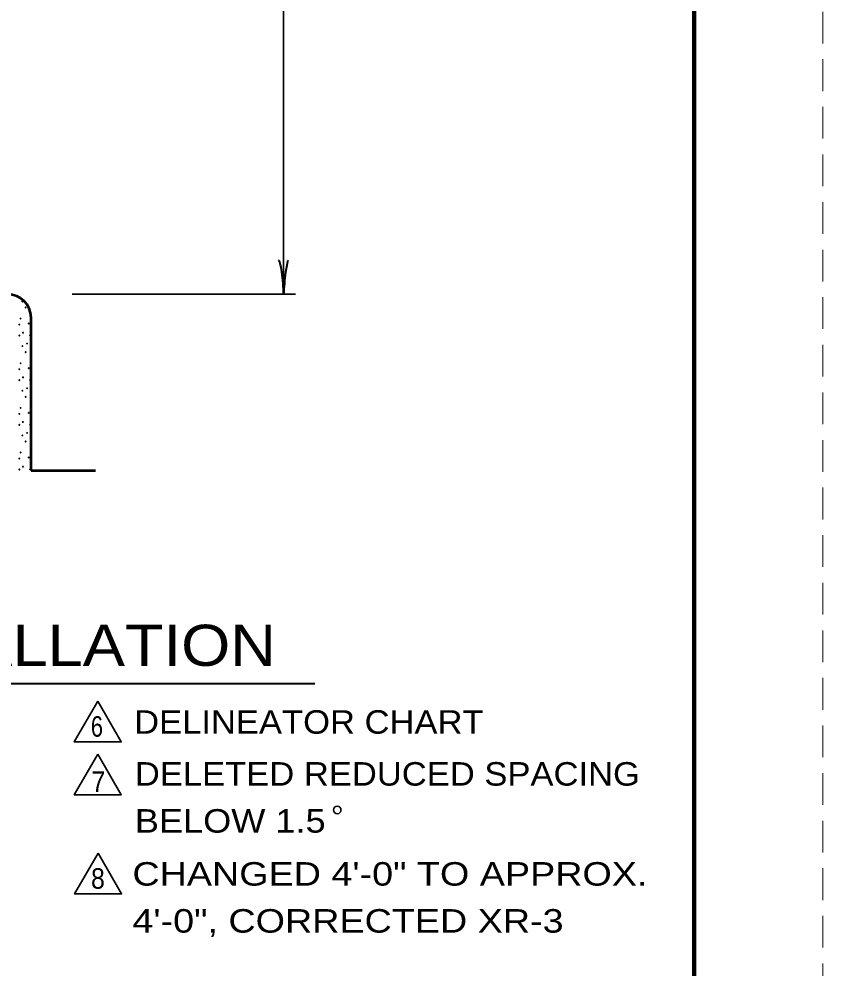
# Model space of a CAD drawing. Extents: x -54 to 626, y -41 to 399.
# Drawn here: x 557.2 to 625.7, y 62.1 to 142.9 of the extents above; entities that cross this region are included whole.
import ezdxf

# ---------------------------------------------------------------- set-up
doc = ezdxf.new("R2010")
doc.units = 0
doc.header["$LTSCALE"] = 0.9
doc.linetypes.add('MEDIUM_DASHED', pattern=[4.5, 3, -1.5])
doc.layers.add('1', color=7, linetype='Continuous', lineweight=35)
doc.layers.add('61', color=7, linetype='Continuous', lineweight=35)

msp = doc.modelspace()

# ---------------------------------------------------------------- linework, layer by layer
at = {"layer": '1', "linetype": 'MEDIUM_DASHED', "lineweight": 13}
msp.add_line((625.6777, 398.7039), (625.6577, -41.3161), dxfattribs=at)
at = {"layer": '1'}
for p, q in [((579.7602, 226.5142), (579.7602, 119.5142)), ((561.7602, 119.5142), (580.7602, 119.5142))]:
    msp.add_line(p, q, dxfattribs=at)
at = {"layer": '1', "lineweight": 53}
for q in [(558.2602, 117.5142), (563.7602, 104.5142)]:
    msp.add_line((558.2602, 104.5142), q, dxfattribs=at)
at = {"layer": '1', "lineweight": 40}
msp.add_line((502.0137, 86.3814), (582.429, 86.3814), dxfattribs=at)
at = {"layer": '1'}
for points in [[(558.2602, 116.0729), (558.1558, 116.0159), (558.2602, 115.9967)], [(558.2602, 112.2729), (558.1558, 112.2159), (558.2602, 112.1967)], [(558.2602, 108.4729), (558.1558, 108.4159), (558.2602, 108.3967)], [(558.2602, 104.6729), (558.1558, 104.6159), (558.2602, 104.5968)]]:
    msp.add_lwpolyline(points, dxfattribs=at)
for points in [[(563.9458, 84.8811), (561.9458, 81.417), (565.9458, 81.417)], [(563.9458, 80.3821), (561.9458, 76.918), (565.9458, 76.918)], [(563.9664, 71.9453), (561.9664, 68.4812), (565.9664, 68.4812)]]:
    msp.add_lwpolyline(points, close=True, dxfattribs=at)
for centre, radius in [((557.5289, 118.8971), 0.0265), ((557.8072, 118.38), 0.0265), ((557.3699, 117.4388), 0.0265), ((557.2639, 116.9266), 0.0265), ((558.0723, 117.0194), 0.0265), ((557.2639, 115.9986), 0.0265), ((557.5819, 116.2373), 0.0265), ((557.5289, 115.0971), 0.0265), ((557.9265, 115.3092), 0.0265), ((557.8072, 114.58), 0.0265), ((557.3699, 113.6388), 0.0265), ((558.0723, 113.2194), 0.0265), ((557.2639, 113.1266), 0.0265), ((557.5819, 112.4373), 0.0265), ((557.2639, 112.1986), 0.0265), ((557.5289, 111.2971), 0.0265), ((557.8072, 110.78), 0.0265), ((557.9265, 111.5092), 0.0265), ((557.2639, 109.3266), 0.0265), ((557.3699, 109.8388), 0.0265), ((558.0723, 109.4194), 0.0265), ((557.2639, 108.3986), 0.0265), ((557.5819, 108.6373), 0.0265), ((557.9265, 107.7092), 0.0265), ((557.5289, 107.4971), 0.0265), ((557.8072, 106.98), 0.0265), ((557.3699, 106.0388), 0.0265), ((557.2639, 105.5266), 0.0265), ((558.0723, 105.6194), 0.0265), ((557.2639, 104.5986), 0.0265), ((557.5819, 104.8373), 0.0265), ((584.3275, 75.6221), 0.3179)]:
    msp.add_circle(centre, radius, dxfattribs=at)
at = {"layer": '1', "lineweight": 53}
msp.add_arc((556.2602, 117.5142), 2, 0, 90, dxfattribs=at)
at = {"layer": '1', "lineweight": 40}
for centre, major_axis, ratio, start_param, end_param in [((579.484, 120.6054), (0.1562, -1.7857), 0.122415, 0.8963533, 3.1415927), ((579.9719, 120.6347), (-0.1757, -1.7565), 0.07063, 3.1407148, 5.41811)]:
    msp.add_ellipse(centre, major_axis=major_axis, ratio=ratio, start_param=start_param, end_param=end_param, dxfattribs=at)
at = {"layer": '61', "lineweight": 158}
msp.add_line((614.6977, 388.7039), (614.7178, -31.3361), dxfattribs=at)

# ---------------------------------------------------------------- texts
at = {"layer": '1'}
for s, height, width, p in [('TYPICAL XR-3 INSTALLATION', 3.5, 1.15, (503.1411, 87.885)), ('DELINEATOR CHART', 2, 1.1, (567.0364, 82.1083)), ('6', 1.75, 0.8, (563.3493, 81.8539)), ('DELETED REDUCED SPACING', 2, 1.1, (567.1, 77.6918)), ('7', 1.75, 0.9, (563.4129, 77.1483)), ('BELOW 1.5', 2, 1.15, (567.1, 73.6918)), ('CHANGED 4\'-0" TO APPROX.', 2, 1.2, (566.8908, 69.1815)), ('8', 1.75, 0.9, (563.3699, 68.9181)), ('4\'-0", CORRECTED XR-3', 2, 1.2, (566.8908, 65.1815))]:
    msp.add_text(s, height=height, dxfattribs=dict(at, width=width)).set_placement(p)

doc.saveas('drawing.dxf')
